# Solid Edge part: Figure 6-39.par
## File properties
Author: CADCIM
Template: Normal.par
Last saved by: CADCIM
Revision: 6
Application: Solid Edge
Accuracy: 0.99
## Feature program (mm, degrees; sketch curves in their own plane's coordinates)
sketch for "unnamed Protrusion 1" plane through (0, 0, 0) normal (0, -1, 0) x-axis (1, 0, 0)
  circle centre (0, 0) radius 43.5332
extrude "unnamed Protrusion 1" add finite 19.05 symmetric
sketch for "ExtrudedProtrusion_2" plane through (0, -9.525, 0) normal (0, -1, 0) x-axis (1, 0, 0)
  circle centre (0, 0) radius 20.3532
extrude "ExtrudedProtrusion_2" add finite 15.875 along +normal
sketch for "unnamed Cutout 1" plane through (0, -9.525, 0) normal (0, -1, 0) x-axis (1, 0, 0)
  arc centre (0, 0) radius 12.0084 from (4.2834, 11.2184) to (-4.2834, 11.2184) cw
  line (-4.2834, 15.2603) -> (-4.2834, 11.2184)
  line (4.2834, 15.2603) -> (-4.2834, 15.2603)
  line (4.2834, 11.2184) -> (4.2834, 15.2603)
extrude "unnamed Cutout 1" cut through along +normal
sketch for "unnamed Cutout 2" plane through (0, -9.525, 0) normal (0, -1, 0) x-axis (1, 0, 0)
  circle centre (0, 33.0061) radius 4
extrude "unnamed Cutout 2" cut through along -normal
pattern "unnamed Pattern 1" of "unnamed Cutout 2"
pattern "unnamed Pattern 2"
fillet "Round_1" radius 2
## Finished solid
Body 1: solid body, 18 faces, 33 edges, 8 vertices.
  Faces by surface: cylinder 11, plane 6, torus 1
  Edges by curve: circle 23, line 10
Bounding box of the edges (mm; curved faces can reach further): 87.066 x 34.925 x 87.066, from (-43.5332, -25.4, -43.5332) to (43.5332, 9.525, 43.5332).
Cylindrical faces by radius (mm): R4 x8, R12.0084 x1, R20.3532 x1, R43.5332 x1
Toroidal faces (ring radius, tube radius in mm): R22.3532 r2 x1
Planar faces by outward normal: +x 1, +y 1, -x 1, -y 2, -z 1
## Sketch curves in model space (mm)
circle centre (0, -9.525, 33.0061) radius 4
line (4.2834, -9.525, 15.2603) -> (-4.2834, -9.525, 15.2603)
line (-4.2834, -9.525, 15.2603) -> (-4.2834, -9.525, 11.2184)
arc centre (0, -9.525, 0) radius 12.0084 from (4.2834, -9.525, 11.2184) through (-0.7167, -9.525, -11.987) to (-4.2834, -9.525, 11.2184)
line (4.2834, -9.525, 11.2184) -> (4.2834, -9.525, 15.2603)
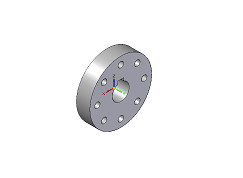
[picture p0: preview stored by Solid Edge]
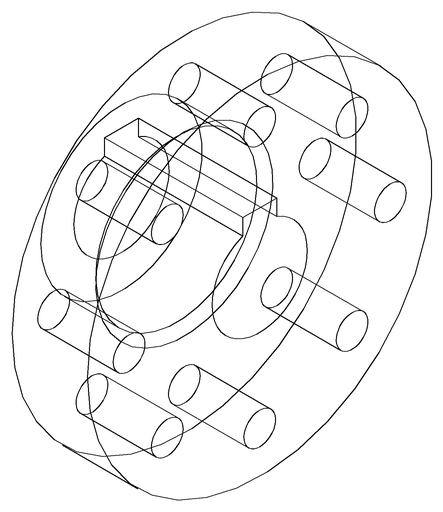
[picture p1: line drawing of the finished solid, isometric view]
